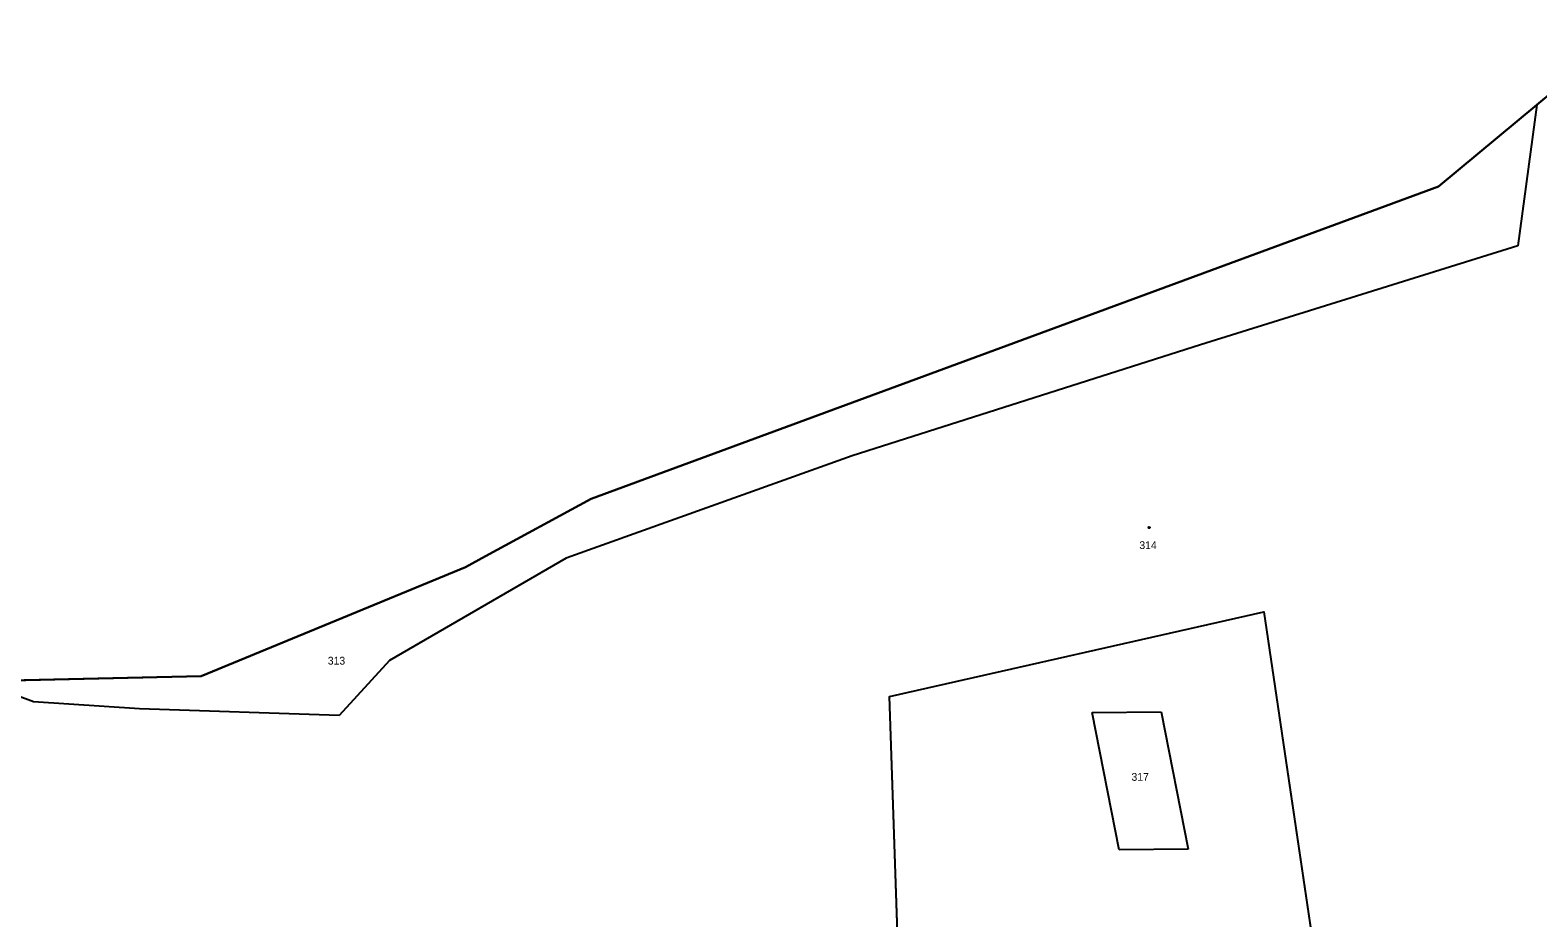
# Model space of a CAD drawing. Extents: x -841286 to -834997, y -1020681 to -1017810.
# Drawn here: x -836086.8 to -835758, y -1019454.5 to -1019260.9 of the extents above; entities that cross this region are included whole.
import ezdxf

# ---------------------------------------------------------------- set-up
doc = ezdxf.new("R2010")
doc.units = 0
for name, color, linetype in [('OVNE_POP', 7, 'Continuous'), ('OVNE_PRE', 7, 'Continuous'), ('OVNE_SET', 7, 'Continuous'), ('OVNI_SET', 7, 'Continuous')]:
    doc.layers.add(name, color=color, linetype=linetype)

msp = doc.modelspace()

# ---------------------------------------------------------------- linework, layer by layer
at = {"layer": 'OVNE_POP'}
msp.add_lwpolyline([(-835842.67, -1019369.27), (-835842.58, -1019369.42), (-835842.67, -1019369.57), (-835842.85, -1019369.57), (-835842.94, -1019369.42), (-835842.85, -1019369.27)], close=True, dxfattribs=at)
at = {"layer": 'OVNE_SET'}
for p, q in [((-835758.25, -1019277.23), (-835738.71, -1019260.93)), ((-835779.63, -1019295.06), (-835758.25, -1019277.23)), ((-835758.25, -1019277.23), (-835762.38, -1019308)), ((-835964.45, -1019363.16), (-835779.63, -1019295.06)), ((-835762.38, -1019308), (-835831.56, -1019329.59)), ((-835831.56, -1019329.59), (-835907.55, -1019353.76)), ((-835907.55, -1019353.76), (-835969.88, -1019376.11)), ((-835987.49, -1019375.64), (-835964.45, -1019363.16)), ((-835991.88, -1019378.03), (-835987.49, -1019375.64)), ((-836049.52, -1019401.8), (-835991.88, -1019378.03)), ((-835969.88, -1019376.11), (-836008.41, -1019398.38)), ((-835899.39, -1019406.23), (-835817.74, -1019387.8)), ((-835817.74, -1019387.8), (-835804.58, -1019476.67)), ((-836008.41, -1019398.38), (-836019.44, -1019410.42)), ((-836149.25, -1019404.08), (-836049.52, -1019401.8)), ((-836086.06, -1019407.39), (-836094.15, -1019404.45)), ((-836062.99, -1019408.93), (-836086.06, -1019407.39)), ((-835896.74, -1019485.76), (-835899.39, -1019406.23)), ((-836019.44, -1019410.42), (-836062.99, -1019408.93)), ((-835855.17, -1019409.75), (-835840.13, -1019409.59)), ((-835849.29, -1019439.69), (-835855.17, -1019409.75)), ((-835840.13, -1019409.59), (-835834.25, -1019439.53)), ((-835834.25, -1019439.53), (-835849.29, -1019439.69))]:
    msp.add_line(p, q, dxfattribs=at)
at = {"layer": 'OVNI_SET'}
for points in [[(-835738.71, -1019260.93), (-835758.25, -1019277.23), (-835779.63, -1019295.06), (-835964.45, -1019363.16), (-835987.49, -1019375.64), (-835991.88, -1019378.03), (-836049.52, -1019401.8), (-836149.25, -1019404.08)], [(-835896.74, -1019485.7), (-835899.39, -1019406.23), (-835817.74, -1019387.8), (-835804.58, -1019476.67)]]:
    msp.add_lwpolyline(points, dxfattribs=at)

# ---------------------------------------------------------------- texts
at = {"layer": 'OVNE_PRE'}
for s, p in [('314', (-835844.9, -1019374.1)), ('313', (-836021.9, -1019399.3)), ('317', (-835846.62, -1019424.64))]:
    msp.add_text(s, height=1.7, dxfattribs=at).set_placement(p)

doc.saveas('drawing.dxf')
